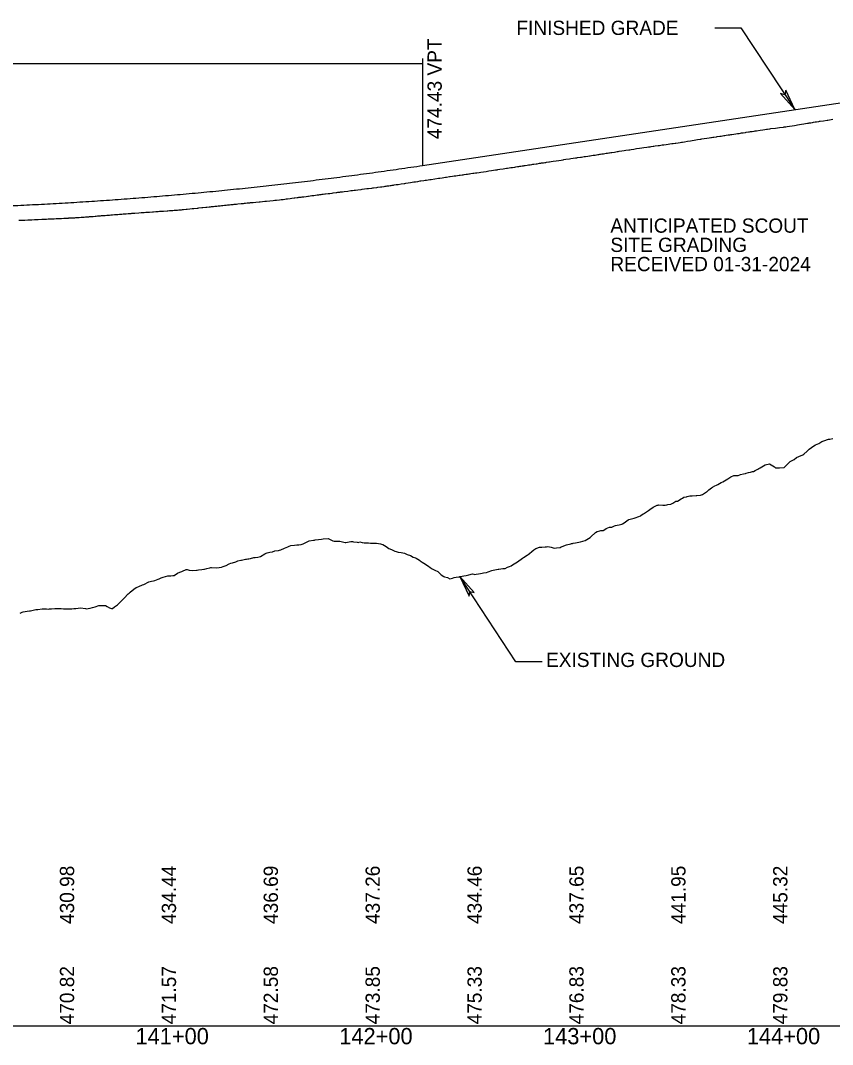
# Model space of a CAD drawing. Extents: x 2017200 to 2047700, y 854850 to 893350.
# Drawn here: x 2023523 to 2023921, y 865091 to 865593 of the extents above; entities that cross this region are included whole.
import ezdxf

# ---------------------------------------------------------------- set-up
doc = ezdxf.new("R2010")
doc.units = 0
for name, color, linetype in [('RD_DDB_Profile_Elev', 7, 'Continuous'), ('RD_DDB_Profile_EX', 7, 'Continuous'), ('RD_DDB_Profile_Lbl', 7, 'Continuous'), ('RD_DDB_Profile_PR', 7, 'Continuous'), ('RD_DDB_StaTX', 7, 'Continuous'), ('RD_DDB_StripGrade', 7, 'Continuous'), ('RD_DDB_VCLbl', 7, 'Continuous'), ('RD_GPK_Profile_Cell', 7, 'Continuous')]:
    doc.layers.add(name, color=color, linetype=linetype)

msp = doc.modelspace()

# ---------------------------------------------------------------- linework, layer by layer
at = {"layer": 'RD_DDB_Profile_Elev'}
msp.add_lwpolyline([(2023521.84, 865495.23), (2023522.68, 865495.27), (2023523.61, 865495.32), (2023524.85, 865495.38), (2023526.31, 865495.45), (2023527.92, 865495.52), (2023528.31, 865495.54), (2023529.61, 865495.6), (2023530.69, 865495.65), (2023531.39, 865495.68), (2023533.15, 865495.76), (2023534.73, 865495.84), (2023535.46, 865495.87), (2023536.17, 865495.9), (2023537.13, 865495.94), (2023537.44, 865495.96), (2023537.84, 865495.98), (2023538.14, 865495.99), (2023538.8, 865496.02), (2023539.14, 865496.03), (2023540.22, 865496.08), (2023541, 865496.12), (2023541.36, 865496.13), (2023542.82, 865496.2), (2023543.95, 865496.25), (2023544.57, 865496.28), (2023544.98, 865496.3), (2023546.16, 865496.35), (2023546.46, 865496.38), (2023547.55, 865496.43), (2023547.93, 865496.45), (2023548.92, 865496.5), (2023549.36, 865496.53), (2023549.75, 865496.55), (2023550.22, 865496.57), (2023550.7, 865496.61), (2023551.39, 865496.65), (2023552.39, 865496.72), (2023552.9, 865496.76), (2023553.45, 865496.8), (2023553.94, 865496.84), (2023554.6, 865496.89), (2023555.04, 865496.92), (2023555.4, 865496.95), (2023556.13, 865497.01), (2023556.48, 865497.04), (2023556.89, 865497.08), (2023557.24, 865497.1), (2023557.73, 865497.14), (2023558.33, 865497.19), (2023559.27, 865497.27), (2023559.8, 865497.31), (2023560.51, 865497.37), (2023561.15, 865497.42), (2023561.95, 865497.49), (2023562.49, 865497.53), (2023563.35, 865497.6), (2023564.15, 865497.67), (2023565.05, 865497.73), (2023565.57, 865497.78), (2023566.42, 865497.84), (2023567.07, 865497.89), (2023567.74, 865497.95), (2023568.8, 865498.03), (2023569.28, 865498.06), (2023569.95, 865498.12), (2023570.5, 865498.16), (2023571.18, 865498.21), (2023571.7, 865498.25), (2023572.45, 865498.31), (2023573.03, 865498.35), (2023573.56, 865498.39), (2023573.94, 865498.42), (2023574.45, 865498.46), (2023575.49, 865498.54), (2023575.95, 865498.57), (2023576.63, 865498.62), (2023577.04, 865498.65), (2023577.37, 865498.68), (2023578.79, 865498.78), (2023580.71, 865498.93), (2023581.93, 865499.01), (2023583.29, 865499.11), (2023584.22, 865499.18), (2023585.47, 865499.27), (2023586.01, 865499.31), (2023587.4, 865499.41), (2023587.86, 865499.44), (2023589.04, 865499.52), (2023590.24, 865499.61), (2023590.94, 865499.66), (2023592.79, 865499.79), (2023594.68, 865499.92), (2023595, 865499.94), (2023595.86, 865500), (2023596.5, 865500.05), (2023597.38, 865500.11), (2023598.15, 865500.16), (2023599.41, 865500.25), (2023599.76, 865500.28), (2023600.33, 865500.32), (2023601.23, 865500.41), (2023601.68, 865500.45), (2023602.15, 865500.5), (2023602.64, 865500.55), (2023603.98, 865500.69), (2023604.53, 865500.75), (2023605.8, 865500.88), (2023606.91, 865501), (2023607.37, 865501.04), (2023607.68, 865501.08), (2023609.29, 865501.24), (2023609.66, 865501.28), (2023610.13, 865501.33), (2023611.67, 865501.49), (2023612.19, 865501.54), (2023613.54, 865501.68), (2023614.14, 865501.74), (2023615.27, 865501.86), (2023615.9, 865501.92), (2023616.44, 865501.98), (2023616.78, 865502.01), (2023617.37, 865502.07), (2023617.98, 865502.14), (2023618.5, 865502.19), (2023619.05, 865502.24), (2023619.71, 865502.31), (2023620.14, 865502.36), (2023620.6, 865502.4), (2023621.34, 865502.48), (2023621.96, 865502.54), (2023622.73, 865502.62), (2023623.58, 865502.71), (2023624.28, 865502.77), (2023625.2, 865502.87), (2023625.96, 865502.95), (2023626.96, 865503.05), (2023627.6, 865503.11), (2023628.35, 865503.19), (2023628.72, 865503.23), (2023629.27, 865503.28), (2023630.88, 865503.44), (2023632.04, 865503.56), (2023632.63, 865503.62), (2023633.11, 865503.67), (2023633.92, 865503.75), (2023635.13, 865503.87), (2023635.49, 865503.91), (2023636.13, 865503.97), (2023636.88, 865504.05), (2023638.22, 865504.18), (2023639.77, 865504.33), (2023640.25, 865504.38), (2023641.47, 865504.5), (2023642.64, 865504.61), (2023643.35, 865504.68), (2023645.07, 865504.85), (2023646.74, 865505.01), (2023647.4, 865505.08), (2023648.29, 865505.17), (2023649.78, 865505.32), (2023650.55, 865505.4), (2023651.11, 865505.46), (2023651.58, 865505.52), (2023652.33, 865505.62), (2023653.1, 865505.72), (2023653.67, 865505.79), (2023654.93, 865505.96), (2023655.76, 865506.07), (2023656.93, 865506.22), (2023657.24, 865506.26), (2023658.51, 865506.42), (2023659, 865506.48), (2023659.31, 865506.52), (2023660.32, 865506.65), (2023660.93, 865506.73), (2023661.69, 865506.83), (2023662.92, 865506.99), (2023663.67, 865507.09), (2023664.07, 865507.14), (2023664.87, 865507.24), (2023665.66, 865507.34), (2023666.69, 865507.47), (2023667.47, 865507.57), (2023668.31, 865507.68), (2023669, 865507.77), (2023669.56, 865507.84), (2023670.19, 865507.92), (2023670.78, 865508), (2023671.22, 865508.05), (2023672.04, 865508.16), (2023672.4, 865508.21), (2023673.6, 865508.36), (2023673.9, 865508.4), (2023674.39, 865508.46), (2023675.63, 865508.62), (2023676.1, 865508.68), (2023677.5, 865508.86), (2023677.91, 865508.92), (2023678.36, 865508.97), (2023679.43, 865509.11), (2023679.76, 865509.15), (2023680.75, 865509.28), (2023681.57, 865509.39), (2023683.28, 865509.61), (2023684.82, 865509.8), (2023685.51, 865509.89), (2023686.35, 865510), (2023687.11, 865510.09), (2023688.18, 865510.23), (2023689.77, 865510.42), (2023690.27, 865510.48), (2023691.55, 865510.64), (2023692.65, 865510.78), (2023693.49, 865510.89), (2023695.14, 865511.09), (2023695.5, 865511.14), (2023695.92, 865511.2), (2023697.49, 865511.4), (2023697.98, 865511.47), (2023699.37, 865511.65), (2023699.91, 865511.73), (2023701.08, 865511.88), (2023701.63, 865511.96), (2023702.18, 865512.03), (2023702.55, 865512.08), (2023703.06, 865512.15), (2023703.48, 865512.22), (2023704.14, 865512.3), (2023704.61, 865512.38), (2023705, 865512.43), (2023705.69, 865512.53), (2023706.08, 865512.59), (2023707, 865512.73), (2023707.45, 865512.8), (2023707.93, 865512.87), (2023709.53, 865513.12), (2023710.88, 865513.32), (2023711.28, 865513.38), (2023711.71, 865513.45), (2023714.09, 865513.81), (2023715.62, 865514.04), (2023716.47, 865514.17), (2023717.69, 865514.36), (2023718.85, 865514.53), (2023719.2, 865514.58), (2023720.66, 865514.8), (2023721.24, 865514.89), (2023721.98, 865515), (2023722.78, 865515.12), (2023723.62, 865515.25), (2023724.13, 865515.32), (2023726, 865515.61), (2023727.79, 865515.87), (2023728.38, 865515.96), (2023729.56, 865516.14), (2023731.28, 865516.39), (2023731.67, 865516.45), (2023733.14, 865516.66), (2023733.54, 865516.72), (2023734.67, 865516.89), (2023735.53, 865517.01), (2023736.32, 865517.12), (2023737.17, 865517.24), (2023737.91, 865517.35), (2023738.4, 865517.42), (2023739.37, 865517.56), (2023739.84, 865517.62), (2023740.4, 865517.71), (2023741.43, 865517.85), (2023742.04, 865517.94), (2023742.67, 865518.02), (2023743.08, 865518.08), (2023743.68, 865518.17), (2023744.64, 865518.3), (2023745.21, 865518.38), (2023746, 865518.49), (2023746.55, 865518.57), (2023747.67, 865518.73), (2023748.51, 865518.85), (2023749.87, 865519.06), (2023751.23, 865519.26), (2023752.54, 865519.46), (2023753.77, 865519.65), (2023754.81, 865519.81), (2023755.71, 865519.95), (2023756.04, 865520), (2023756.54, 865520.07), (2023756.96, 865520.14), (2023757.86, 865520.27), (2023759.57, 865520.53), (2023761.22, 865520.78), (2023761.73, 865520.85), (2023763.22, 865521.08), (2023763.64, 865521.14), (2023764.11, 865521.21), (2023765.23, 865521.38), (2023765.74, 865521.46), (2023766.49, 865521.57), (2023767.17, 865521.67), (2023767.71, 865521.75), (2023768.21, 865521.83), (2023768.87, 865521.93), (2023769.45, 865522.01), (2023769.88, 865522.08), (2023770.33, 865522.15), (2023771.34, 865522.29), (2023772, 865522.4), (2023772.75, 865522.51), (2023773.64, 865522.64), (2023774.12, 865522.71), (2023774.57, 865522.78), (2023775.64, 865522.94), (2023776.18, 865523.02), (2023777.43, 865523.21), (2023777.99, 865523.3), (2023778.4, 865523.36), (2023779.39, 865523.51), (2023779.91, 865523.59), (2023780.41, 865523.66), (2023780.78, 865523.72), (2023781.86, 865523.88), (2023782.27, 865523.94), (2023783.16, 865524.08), (2023784.03, 865524.21), (2023785.54, 865524.44), (2023786.84, 865524.64), (2023787.93, 865524.8), (2023788.91, 865524.95), (2023789.22, 865525), (2023790.33, 865525.16), (2023792.08, 865525.42), (2023792.69, 865525.51), (2023793.95, 865525.69), (2023795.07, 865525.86), (2023795.6, 865525.93), (2023795.92, 865525.98), (2023797.46, 865526.21), (2023797.93, 865526.28), (2023799.33, 865526.48), (2023799.93, 865526.58), (2023801.15, 865526.76), (2023801.88, 865526.87), (2023802.22, 865526.92), (2023802.88, 865527.02), (2023803.71, 865527.15), (2023804.6, 865527.28), (2023805.38, 865527.4), (2023805.93, 865527.48), (2023806.45, 865527.56), (2023806.98, 865527.64), (2023807.34, 865527.7), (2023807.98, 865527.8), (2023808.78, 865527.92), (2023809.46, 865528.03), (2023810.1, 865528.12), (2023810.77, 865528.23), (2023811.42, 865528.33), (2023811.74, 865528.38), (2023812.34, 865528.47), (2023812.92, 865528.56), (2023814.13, 865528.74), (2023815.5, 865528.95), (2023815.92, 865529.02), (2023816.51, 865529.11), (2023817.82, 865529.31), (2023818.89, 865529.47), (2023819.74, 865529.6), (2023821.27, 865529.83), (2023821.65, 865529.89), (2023822.38, 865530), (2023823.65, 865530.19), (2023825.03, 865530.39), (2023826.42, 865530.6), (2023827.51, 865530.76), (2023828.6, 865530.92), (2023830, 865531.12), (2023830.8, 865531.24), (2023831.32, 865531.31), (2023831.68, 865531.36), (2023832.15, 865531.43), (2023833.18, 865531.58), (2023833.54, 865531.63), (2023834.17, 865531.72), (2023835.56, 865531.92), (2023836.28, 865532.02), (2023837.49, 865532.19), (2023837.94, 865532.26), (2023838.39, 865532.32), (2023839.43, 865532.47), (2023840.42, 865532.61), (2023841.26, 865532.73), (2023842.28, 865532.87), (2023842.92, 865532.96), (2023843.9, 865533.1), (2023844.33, 865533.16), (2023845.42, 865533.32), (2023846.32, 865533.46), (2023847.03, 865533.56), (2023847.47, 865533.63), (2023848.53, 865533.8), (2023849.94, 865534.02), (2023851.49, 865534.27), (2023852.23, 865534.38), (2023853.22, 865534.54), (2023854.95, 865534.81), (2023856.13, 865535), (2023856.6, 865535.07), (2023857, 865535.14), (2023858.19, 865535.32), (2023859.4, 865535.51), (2023860.56, 865535.69), (2023861.41, 865535.81), (2023861.76, 865535.87), (2023862.48, 865535.98), (2023862.87, 865536.03), (2023864.14, 865536.23), (2023864.53, 865536.29), (2023865.83, 865536.48), (2023866.57, 865536.6), (2023867.86, 865536.79), (2023868.25, 865536.85), (2023868.91, 865536.95), (2023869.99, 865537.11), (2023870.71, 865537.22), (2023871.29, 865537.31), (2023871.77, 865537.38), (2023872.65, 865537.51), (2023873.67, 865537.66), (2023874.56, 865537.8), (2023875.27, 865537.9), (2023876.05, 865538.02), (2023876.4, 865538.08), (2023876.92, 865538.15), (2023877.29, 865538.21), (2023878.46, 865538.39), (2023878.79, 865538.44), (2023879.95, 865538.61), (2023880.34, 865538.67), (2023880.82, 865538.74), (2023881.39, 865538.83), (2023881.78, 865538.89), (2023882.62, 865539.02), (2023883.2, 865539.1), (2023883.81, 865539.19), (2023885.58, 865539.46), (2023886.97, 865539.66), (2023887.96, 865539.81), (2023888.81, 865539.94), (2023889.25, 865540), (2023890.34, 865540.13), (2023890.94, 865540.21), (2023893.2, 865540.49), (2023895.13, 865540.74), (2023897.06, 865540.99), (2023897.49, 865541.05), (2023898.18, 865541.13), (2023898.89, 865541.22), (2023900.1, 865541.41), (2023901.37, 865541.62), (2023902.43, 865541.79), (2023903.31, 865541.94), (2023904.01, 865542.06), (2023904.92, 865542.22), (2023905.91, 865542.38), (2023907.02, 865542.57), (2023907.9, 865542.71), (2023908.79, 865542.87), (2023909.4, 865542.96), (2023909.75, 865543.02), (2023910.49, 865543.14), (2023911.27, 865543.27), (2023911.83, 865543.36), (2023912.64, 865543.48), (2023913.28, 865543.59), (2023914.38, 865543.75), (2023914.72, 865543.81), (2023915.11, 865543.86), (2023916.77, 865544.11), (2023918.58, 865544.39), (2023918.92, 865544.44), (2023920.46, 865544.67), (2023921.31, 865544.8)], dxfattribs=at)
at = {"layer": 'RD_DDB_Profile_EX'}
msp.add_lwpolyline([(2023522.59, 865302.49), (2023523.55, 865302.92), (2023523.97, 865303.1), (2023525.93, 865303.43), (2023527.08, 865303.59), (2023527.52, 865303.69), (2023528.31, 865303.86), (2023530.19, 865304.28), (2023530.69, 865304.32), (2023531.19, 865304.37), (2023533.3, 865304.63), (2023535.46, 865304.58), (2023536.4, 865304.42), (2023536.98, 865304.56), (2023537.84, 865304.63), (2023539.6, 865304.79), (2023540.22, 865304.8), (2023542.6, 865304.83), (2023543.75, 865304.56), (2023544.98, 865304.57), (2023545.69, 865304.57), (2023547.36, 865304.64), (2023547.85, 865304.65), (2023548.78, 865304.73), (2023549.75, 865304.86), (2023552.13, 865305.1), (2023554.51, 865304.72), (2023554.95, 865304.7), (2023556.89, 865305.02), (2023558.03, 865305.26), (2023559.32, 865305.6), (2023561.1, 865306.21), (2023561.83, 865306.24), (2023564.35, 865306.29), (2023565.15, 865305.79), (2023566.42, 865305.19), (2023567.25, 865304.79), (2023567.83, 865304.85), (2023568.8, 865305.56), (2023570.32, 865306.67), (2023571.18, 865307.51), (2023571.72, 865308.04), (2023573.56, 865309.86), (2023575.58, 865311.91), (2023575.95, 865312.28), (2023576.44, 865312.77), (2023578.33, 865314.21), (2023579.5, 865315.09), (2023579.9, 865315.26), (2023580.71, 865315.62), (2023582.56, 865316.42), (2023583.2, 865316.62), (2023585.61, 865317.8), (2023586.97, 865318.13), (2023587.86, 865318.35), (2023588.67, 865318.56), (2023590.24, 865319.19), (2023590.71, 865319.37), (2023591.72, 865319.84), (2023592.62, 865320.12), (2023595, 865320.85), (2023596.41, 865320.86), (2023597.38, 865320.93), (2023598.1, 865321.06), (2023599.76, 865322.05), (2023600.85, 865322.7), (2023601.76, 865322.99), (2023602.15, 865323.18), (2023603.89, 865324.01), (2023604.53, 865323.85), (2023605.39, 865323.62), (2023606.93, 865323.36), (2023608.99, 865323.6), (2023609.29, 865323.63), (2023609.97, 865323.7), (2023611.67, 865323.98), (2023612.57, 865324.12), (2023613, 865324.1), (2023614.06, 865324.36), (2023615.51, 865324.71), (2023616.13, 865324.84), (2023616.44, 865324.83), (2023619.07, 865324.75), (2023621.28, 865325.08), (2023622.1, 865325.46), (2023623.17, 865325.73), (2023623.58, 865325.95), (2023625.12, 865326.77), (2023625.96, 865326.99), (2023626.65, 865327.16), (2023628.35, 865327.71), (2023629.31, 865328.1), (2023630.73, 865328.44), (2023631.17, 865328.54), (2023633.11, 865328.94), (2023633.56, 865329.03), (2023634.19, 865329.14), (2023634.7, 865329.13), (2023635.49, 865329.33), (2023637.22, 865329.77), (2023637.87, 865329.87), (2023639.06, 865330.05), (2023640.38, 865330.29), (2023642.64, 865331.63), (2023643.25, 865332), (2023643.76, 865332.15), (2023645.02, 865332.4), (2023646.27, 865332.63), (2023647.4, 865333.03), (2023649.28, 865333.21), (2023649.78, 865333.37), (2023650.46, 865333.59), (2023652.3, 865334.32), (2023653.79, 865334.98), (2023654.55, 865335.37), (2023655.31, 865335.77), (2023657.09, 865335.89), (2023658.32, 865335.99), (2023659.31, 865336.1), (2023660.38, 865336.22), (2023661.33, 865336.5), (2023661.69, 865336.69), (2023663.65, 865337.72), (2023664.34, 865338), (2023666.45, 865338.32), (2023666.9, 865338.39), (2023667.35, 865338.47), (2023668.84, 865338.66), (2023670.36, 865338.88), (2023671.22, 865339.01), (2023673.63, 865339.2), (2023675.98, 865337.99), (2023676.55, 865337.79), (2023678.36, 865337.84), (2023679.38, 865337.87), (2023680.75, 865337.52), (2023681.91, 865337.22), (2023682.38, 865337.14), (2023683.13, 865337.32), (2023684.78, 865337.72), (2023685.51, 865337.66), (2023686.06, 865337.57), (2023687.89, 865337.28), (2023688.39, 865337.2), (2023689.19, 865337.47), (2023690.27, 865337.25), (2023691.39, 865337.02), (2023692.65, 865336.99), (2023693.43, 865336.97), (2023694.4, 865336.81), (2023695.04, 865336.84), (2023696.34, 865336.91), (2023697.42, 865336.9), (2023699.26, 865336.55), (2023699.8, 865336.35), (2023700.4, 865336.14), (2023702.19, 865335.22), (2023703.4, 865334.24), (2023704.67, 865333.79), (2023706.4, 865332.86), (2023706.94, 865332.71), (2023708.08, 865332.4), (2023709.4, 865332.35), (2023711.05, 865332.01), (2023711.71, 865331.68), (2023712.4, 865331.34), (2023714.09, 865330.77), (2023715.4, 865330.03), (2023716.47, 865329.64), (2023716.79, 865329.52), (2023718.4, 865328.58), (2023718.85, 865328.22), (2023719.79, 865327.47), (2023721.41, 865326.58), (2023723.03, 865325.47), (2023723.62, 865325.05), (2023724.41, 865324.5), (2023726.06, 865323.64), (2023727.41, 865322.96), (2023728.38, 865322), (2023729.1, 865321.29), (2023730.41, 865320.42), (2023730.76, 865320.33), (2023732.16, 865319.99), (2023733.41, 865319.37), (2023734.61, 865319.74), (2023735.53, 865319.93), (2023736.41, 865320.11), (2023737.91, 865320.36), (2023738.31, 865320.42), (2023739.41, 865320.73), (2023740.29, 865320.85), (2023741.4, 865320.99), (2023742.67, 865321.31), (2023744.51, 865321.75), (2023745.05, 865321.6), (2023745.42, 865321.5), (2023746.25, 865321.68), (2023747.44, 865321.86), (2023748.42, 865322.01), (2023749.14, 865322.21), (2023749.82, 865322.28), (2023751.42, 865322.43), (2023752.2, 865322.76), (2023753.94, 865323.49), (2023754.58, 865323.57), (2023757.11, 865324.05), (2023757.43, 865324.11), (2023759.34, 865324.34), (2023760.44, 865324.47), (2023761.73, 865325.04), (2023762.61, 865325.43), (2023763.44, 865325.81), (2023764.11, 865326.22), (2023766.49, 865327.66), (2023769.03, 865329.55), (2023769.46, 865329.81), (2023771.25, 865330.89), (2023771.83, 865331.23), (2023772.47, 865331.7), (2023773.64, 865332.75), (2023774.62, 865333.63), (2023775.48, 865334.2), (2023776.02, 865334.38), (2023777.41, 865334.83), (2023778.49, 865334.9), (2023780.18, 865334.99), (2023780.78, 865335.08), (2023781.5, 865335.18), (2023783.16, 865334.88), (2023784.51, 865334.47), (2023785.7, 865334.51), (2023787.53, 865334.78), (2023787.93, 865335), (2023788.45, 865335.27), (2023790.54, 865336.11), (2023792.69, 865336.54), (2023793.12, 865336.63), (2023793.56, 865336.61), (2023793.92, 865336.8), (2023795.07, 865337.03), (2023796.58, 865337.32), (2023797.45, 865337.53), (2023799.83, 865338.15), (2023802.22, 865339.6), (2023802.62, 865339.88), (2023804.76, 865342.1), (2023805.64, 865342.64), (2023806.98, 865342.93), (2023807.45, 865343.03), (2023808.67, 865343.13), (2023809.36, 865343.54), (2023810.13, 865343.99), (2023811.74, 865344.71), (2023812.8, 865344.75), (2023814.13, 865345.28), (2023814.72, 865345.52), (2023815.47, 865345.63), (2023816.51, 865345.86), (2023817.75, 865346.13), (2023818.12, 865346.27), (2023818.89, 865346.87), (2023820.79, 865348.35), (2023821.27, 865348.46), (2023823.81, 865349.06), (2023824.35, 865349.35), (2023826.03, 865350.01), (2023826.85, 865350.33), (2023827.93, 865351), (2023828.42, 865351.29), (2023829.88, 865352.17), (2023830.8, 865352.84), (2023831.54, 865353.39), (2023833.18, 865354.52), (2023835.17, 865355.48), (2023835.56, 865355.55), (2023835.96, 865355.62), (2023837.94, 865355.52), (2023839.01, 865355.49), (2023839.84, 865355.66), (2023840.33, 865355.75), (2023841.73, 865356.01), (2023842.05, 865356.11), (2023842.71, 865356.49), (2023844.31, 865357.42), (2023845.1, 865357.51), (2023846.9, 865358.56), (2023847.47, 865358.94), (2023848.15, 865359.39), (2023849.47, 865359.61), (2023849.85, 865359.69), (2023851.2, 865359.99), (2023852.23, 865360.11), (2023854.26, 865360.19), (2023854.62, 865360.18), (2023856.35, 865360.45), (2023857.32, 865360.68), (2023859.38, 865362.05), (2023859.71, 865362.27), (2023860.38, 865363.01), (2023861.76, 865363.97), (2023862.25, 865364.3), (2023863.44, 865364.96), (2023864.14, 865365.35), (2023864.79, 865365.7), (2023866.53, 865366.62), (2023867.32, 865366.98), (2023868.91, 865367.88), (2023869.85, 865368.34), (2023871.29, 865369.36), (2023872.65, 865370.07), (2023873.67, 865370.05), (2023874.88, 865370.02), (2023875.72, 865370.42), (2023876.05, 865370.5), (2023877.39, 865370.83), (2023878.43, 865371.09), (2023878.8, 865371.18), (2023879.9, 865371.46), (2023880.82, 865371.72), (2023881.88, 865372.02), (2023882.39, 865372.07), (2023883.2, 865372.47), (2023884.57, 865373.17), (2023884.96, 865373.4), (2023885.58, 865373.77), (2023888.1, 865375.28), (2023890.17, 865375.78), (2023892.72, 865374.31), (2023893.09, 865373.85), (2023895.11, 865373.83), (2023897.49, 865374.01), (2023899.87, 865376.5), (2023900.43, 865376.89), (2023902.25, 865377.96), (2023903.53, 865378.82), (2023904.64, 865379.34), (2023906.64, 865380.12), (2023907.02, 865380.44), (2023908.73, 865381.93), (2023909.75, 865382.9), (2023911.97, 865384.52), (2023912.87, 865385.1), (2023914.4, 865385.81), (2023915.98, 865386.72), (2023916.83, 865387), (2023919.25, 865387.8), (2023919.75, 865387.9), (2023921.31, 865388.25)], dxfattribs=at)
at = {"layer": 'RD_DDB_Profile_Lbl'}
for p, q in [((2023765.77, 865278.71), (2023738.31, 865320.42)), ((2023778.63, 865278.71), (2023765.77, 865278.71))]:
    msp.add_line(p, q, dxfattribs=at)
msp.add_lwpolyline([(2023863.32, 865589.72), (2023876.18, 865589.72), (2023902.63, 865549.54)], dxfattribs=at)
for points in [[(2023902.63, 865549.54), (2023898.17, 865559.04), (2023897.8, 865556.88), (2023895.66, 865557.4)], [(2023738.31, 865320.42), (2023742.76, 865310.92), (2023743.14, 865313.08), (2023745.27, 865312.57)]]:
    msp.add_lwpolyline(points, close=True, dxfattribs=at)
at = {"layer": 'RD_DDB_Profile_PR'}
msp.add_line((2023720, 865522.15), (2024002.5, 865564.53), dxfattribs=at)
msp.add_spline([(2023140, 865522.15), (2023151.6, 865520.44), (2023163.2, 865518.81), (2023174.8, 865517.24), (2023186.4, 865515.75), (2023198, 865514.32), (2023209.6, 865512.96), (2023221.2, 865511.68), (2023232.8, 865510.46), (2023244.4, 865509.31), (2023256, 865508.23), (2023267.6, 865507.22), (2023279.2, 865506.28), (2023290.8, 865505.41), (2023302.4, 865504.61), (2023314, 865503.88), (2023325.6, 865503.22), (2023337.2, 865502.63), (2023348.8, 865502.11), (2023360.4, 865501.65), (2023372, 865501.27), (2023383.6, 865500.96), (2023395.2, 865500.71), (2023406.8, 865500.54), (2023418.4, 865500.43), (2023430, 865500.4), (2023441.6, 865500.43), (2023453.2, 865500.54), (2023464.8, 865500.71), (2023476.4, 865500.96), (2023488, 865501.27), (2023499.6, 865501.65), (2023511.2, 865502.11), (2023522.8, 865502.63), (2023534.4, 865503.22), (2023546, 865503.88), (2023557.6, 865504.61), (2023569.2, 865505.41), (2023580.8, 865506.28), (2023592.4, 865507.22), (2023604, 865508.23), (2023615.6, 865509.31), (2023627.2, 865510.46), (2023638.8, 865511.68), (2023650.4, 865512.96), (2023662, 865514.32), (2023673.6, 865515.75), (2023685.2, 865517.24), (2023696.8, 865518.81), (2023708.4, 865520.44), (2023720, 865522.15)], degree=3, dxfattribs=at)
at = {"layer": 'RD_DDB_VCLbl'}
for p, q in [((2023720, 865574.65), (2023720, 865522.15)), ((2023140, 865572.15), (2023720, 865572.15))]:
    msp.add_line(p, q, dxfattribs=at)
at = {"layer": 'RD_GPK_Profile_Cell'}
msp.add_line((2020500, 865100), (2029700, 865100), dxfattribs=at)

# ---------------------------------------------------------------- texts
at = {"layer": 'RD_DDB_Profile_Elev'}
for s, p in [('ANTICIPATED SCOUT', (2023812.13, 865489.14)), ('SITE GRADING', (2023812.13, 865479.71)), ('RECEIVED 01-31-2024', (2023812.13, 865470.29))]:
    msp.add_text(s, height=7, dxfattribs=at).set_placement(p)
at = {"layer": 'RD_DDB_Profile_Lbl'}
for s, p in [('FINISHED GRADE', (2023766, 865586.17)), ('EXISTING GROUND', (2023780.57, 865276.09))]:
    msp.add_text(s, height=7, dxfattribs=at).set_placement(p)
at = {"layer": 'RD_DDB_StaTX'}
for s, p in [('141+00', (2023579.1, 865091)), ('141+00', (2023579.1, 865091)), ('142+00', (2023679.1, 865091)), ('142+00', (2023679.1, 865091)), ('143+00', (2023779.1, 865091)), ('143+00', (2023779.1, 865091)), ('144+00', (2023879.1, 865091)), ('144+00', (2023879.1, 865091))]:
    msp.add_text(s, height=8, dxfattribs=at).set_placement(p)
at = {"layer": 'RD_DDB_StripGrade'}
for s, p in [('474.43 VPT', (2023729.39, 865535.04)), ('430.98', (2023549, 865150)), ('434.44', (2023599, 865150)), ('436.69', (2023649, 865150)), ('437.26', (2023699, 865150)), ('434.46', (2023749, 865150)), ('437.65', (2023799, 865150)), ('441.95', (2023849, 865150)), ('445.32', (2023899, 865150)), ('470.82', (2023549, 865100.75)), ('471.57', (2023599, 865100.75)), ('472.58', (2023649, 865100.75)), ('473.85', (2023699, 865100.75)), ('475.33', (2023749, 865100.75)), ('476.83', (2023799, 865100.75)), ('478.33', (2023849, 865100.75)), ('479.83', (2023899, 865100.75))]:
    msp.add_text(s, height=7, rotation=90, dxfattribs=at).set_placement(p)

doc.saveas('drawing.dxf')
